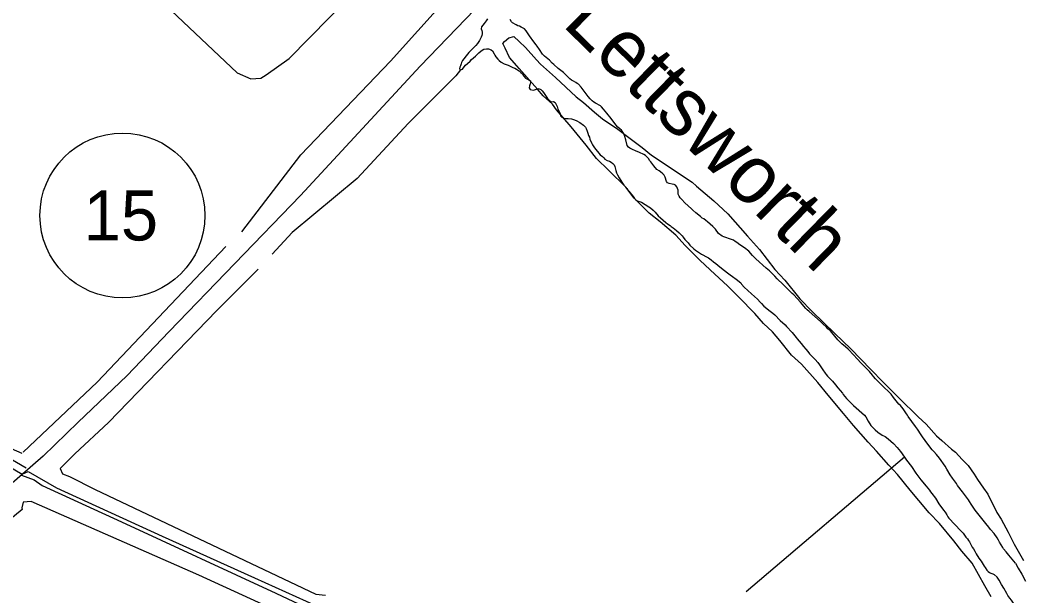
# Model space of a CAD drawing. Extents: x 3161665 to 3199565, y 885729 to 911164.
# Drawn here: x 3167700 to 3169703, y 903568 to 904720 of the extents above; entities that cross this region are included whole.
import ezdxf

# ---------------------------------------------------------------- set-up
doc = ezdxf.new("R2010")
doc.units = 0
for name, color, linetype in [('V-RIVR-IDEN', 7, 'Continuous'), ('V-ROAD-CNTR', 7, 'Continuous'), ('V-ROAD-IDEN', 7, 'Continuous'), ('V-SITE-VEGE', 7, 'Continuous'), ('V-TOPO-SHOR', 7, 'Continuous')]:
    doc.layers.add(name, color=color, linetype=linetype)

msp = doc.modelspace()

# ---------------------------------------------------------------- linework, layer by layer
at = {"layer": 'V-ROAD-CNTR'}
for points in [[(3168682.8, 904817.2), (3168682.1, 904817.3), (3168500.2, 904627.3), (3168260.8, 904368.7), (3167998.1, 904096.6), (3167913.2, 904008.1), (3167816, 903915.2), (3167746.2, 903847.5), (3167631.8, 903748), (3167456.1, 903609.1), (3167355.1, 903531.9), (3167229.6, 903443.7), (3167105.2, 903362.7), (3166973.6, 903283.3), (3166847.9, 903211.6), (3166848.1, 903211.9), (3166676.1, 903125.4), (3166497, 903041.3), (3166200.2, 902917.8), (3166006.1, 902838.5), (3165919.5, 902802.7)], [(3165917.6, 904384.3), (3165969.9, 904376.5), (3166091.1, 904355.3), (3166225.4, 904330.9), (3166351.9, 904300.8), (3166475.2, 904271.7), (3166619.8, 904232), (3166778.1, 904186.6), (3166922.7, 904139.3), (3167057.1, 904090.8), (3167183.4, 904042.2), (3167327.3, 903982.6), (3167459.2, 903926.5), (3167588.6, 903869.4), (3167666.6, 903833.5), (3167704.5, 903811.2)], [(3165919.8, 904399.1), (3165972.3, 904391.3), (3166093.7, 904370.1), (3166228.5, 904345.6), (3166355.4, 904315.4), (3166478.9, 904286.2), (3166623.9, 904246.5), (3166782.5, 904201), (3166927.5, 904153.5), (3167062.3, 904104.9), (3167189, 904056.2), (3167333.1, 903996.5), (3167465.2, 903940.2), (3167594.7, 903883.1), (3167673.5, 903846.8), (3167712.1, 903824.1)], [(3167703, 903809.6), (3167728.2, 903800.1), (3167744.2, 903788.6), (3167902.5, 903716.1), (3168211.5, 903573.2), (3168383, 903492.7), (3168410.7, 903477.2), (3168439.1, 903458.2), (3168484.2, 903425.5), (3168516.8, 903396), (3168566.5, 903352.3), (3168599.2, 903323.2), (3168649.1, 903270.5), (3168697.7, 903213.9), (3168754.3, 903137.6), (3168806.2, 903050.7), (3168857.4, 902953.1), (3168893.3, 902865.9), (3168919.2, 902776.6), (3168937.2, 902680.9), (3168945, 902608.9)], [(3167704.5, 903811.2), (3167716, 903816.7), (3167772.8, 903783.8), (3167983.8, 903687), (3168168.5, 903603.9), (3168293, 903548.2), (3168375.8, 903504.9), (3168429.9, 903476.8), (3168470.8, 903453.3), (3168514, 903420.1), (3168562.2, 903368), (3168623.7, 903312.2), (3168688.9, 903242.9), (3168746.1, 903172.8), (3168783.7, 903113.8), (3168823.8, 903044.9), (3168870.5, 902954.5), (3168900.3, 902877.7), (3168928.1, 902790.3), (3168946.2, 902701.5), (3168955.2, 902630.5)]]:
    msp.add_lwpolyline(points, dxfattribs=at)
at = {"layer": 'V-ROAD-IDEN'}
msp.add_circle((3167904.7, 904328.9), 165, dxfattribs=at)
at = {"layer": 'V-SITE-VEGE'}
for p, q in [((3168668.8, 904676.9), (3168677.4, 904684.2)), ((3168677.4, 904684.2), (3168687.1, 904686.7)), ((3168687.1, 904686.7), (3168698.1, 904676.9)), ((3168665.2, 904673.2), (3168668.8, 904676.9)), ((3168670.1, 904663.4), (3168665.2, 904673.2)), ((3168678.7, 904645.2), (3168670.1, 904663.4)), ((3168698.1, 904676.9), (3168710.3, 904664.8)), ((3168710.3, 904664.8), (3168732.4, 904640.4)), ((3168693.3, 904628.1), (3168678.7, 904645.2)), ((3168698.2, 904623.2), (3168693.3, 904628.1)), ((3168734.9, 904581.8), (3168698.2, 904623.2)), ((3168732.4, 904640.4), (3168740.9, 904631.9)), ((3168740.9, 904631.9), (3168770.3, 904605.1)), ((3168770.3, 904605.1), (3168811.9, 904566.1)), ((3168746, 904568.4), (3168734.9, 904581.8)), ((3168764.3, 904551.4), (3168746, 904568.4)), ((3168811.9, 904566.1), (3168826.5, 904555.2)), ((3168772.9, 904540.4), (3168764.3, 904551.4)), ((3168826.5, 904555.2), (3168848.5, 904535.7)), ((3168802.2, 904506.3), (3168772.9, 904540.4)), ((3168848.5, 904535.7), (3168864.4, 904522.3)), ((3168864.4, 904522.3), (3168895, 904501.7)), ((3168831.6, 904469.8), (3168802.2, 904506.3)), ((3168895, 904501.7), (3168914.5, 904487.1)), ((3168914.5, 904487.1), (3168943.9, 904465.2)), ((3168852.4, 904443), (3168831.6, 904469.8)), ((3168943.9, 904465.2), (3168962.2, 904449.3)), ((3168876.9, 904418.6), (3168852.4, 904443)), ((3168962.2, 904449.3), (3168994, 904428.7)), ((3168994, 904428.7), (3169012.3, 904416.5)), ((3168911.1, 904385.8), (3168876.9, 904418.6)), ((3169012.3, 904416.5), (3169044.1, 904395.8)), ((3168928.2, 904363.8), (3168911.1, 904385.8)), ((3169044.1, 904395.8), (3169052.7, 904387.3)), ((3169052.7, 904387.3), (3169086.9, 904358.1)), ((3168957.6, 904333.4), (3168928.2, 904363.8)), ((3169086.9, 904358.1), (3169115, 904332.5)), ((3168979.6, 904316.4), (3168957.6, 904333.4)), ((3169115, 904332.5), (3169154.2, 904287.5)), ((3169011.4, 904289.6), (3168979.6, 904316.4)), ((3169029.8, 904268.9), (3169011.4, 904289.6)), ((3169154.2, 904287.5), (3169178.6, 904260.7)), ((3169059.1, 904239.7), (3169029.8, 904268.9)), ((3169178.6, 904260.7), (3169209.2, 904220.5)), ((3169079.9, 904220.2), (3169059.1, 904239.7)), ((3169115.4, 904187.3), (3169079.9, 904220.2)), ((3169209.2, 904220.5), (3169228.8, 904199.8)), ((3169137.4, 904165.4), (3169115.4, 904187.3)), ((3169228.8, 904199.8), (3169259.4, 904162)), ((3169169.2, 904132.5), (3169137.4, 904165.4)), ((3169259.4, 904162), (3169283.9, 904136.5)), ((3169186.3, 904113.1), (3169169.2, 904132.5)), ((3169283.9, 904136.5), (3169329.1, 904092.6)), ((3169204.7, 904096), (3169186.3, 904113.1)), ((3169219.3, 904079), (3169204.7, 904096)), ((3169329.1, 904092.6), (3169360.9, 904062.2)), ((3169242.6, 904049.7), (3169219.3, 904079)), ((3169360.9, 904062.2), (3169401.3, 904020.8)), ((3169262.2, 904031.5), (3169242.6, 904049.7)), ((3169295.2, 903994.9), (3169262.2, 904031.5)), ((3169401.3, 904020.8), (3169425.8, 903995.2)), ((3169316, 903969.4), (3169295.2, 903994.9)), ((3169425.8, 903995.2), (3169457.6, 903963.6)), ((3169346.6, 903932.8), (3169316, 903969.4)), ((3169457.6, 903963.6), (3169495.5, 903925.8)), ((3169366.2, 903908.5), (3169346.6, 903932.8)), ((3169495.5, 903925.8), (3169511.4, 903911.2)), ((3169395.5, 903875.6), (3169366.2, 903908.5)), ((3169511.4, 903911.2), (3169532.2, 903888.1)), ((3169532.2, 903888.1), (3169543.2, 903878.4)), ((3169412.6, 903857.3), (3169395.5, 903875.6)), ((3169543.2, 903878.4), (3169562.7, 903861.3)), ((3169562.7, 903861.3), (3169570.1, 903855.2)), ((3169437.1, 903829.3), (3169412.6, 903857.3)), ((3169570.1, 903855.2), (3169583.5, 903840.6)), ((3169454.2, 903811), (3169437.1, 903829.3)), ((3169583.5, 903840.6), (3169595.8, 903828.5)), ((3169595.8, 903828.5), (3169608, 903811.4)), ((3169479.9, 903779.4), (3169454.2, 903811)), ((3169608, 903811.4), (3169614.1, 903800.4)), ((3169614.1, 903800.4), (3169626.4, 903783.4)), ((3169626.4, 903783.4), (3169634.9, 903771.2)), ((3169497.1, 903758.7), (3169479.9, 903779.4)), ((3169634.9, 903771.2), (3169653.3, 903734.6)), ((3169517.9, 903734.3), (3169497.1, 903758.7)), ((3169538.7, 903712.4), (3169517.9, 903734.3)), ((3169653.3, 903734.6), (3169661.9, 903721.2)), ((3169661.9, 903721.2), (3169675.4, 903695.6)), ((3169566.8, 903678.3), (3169538.7, 903712.4)), ((3169675.4, 903695.6), (3169687.6, 903671.2)), ((3169582.7, 903657.6), (3169566.8, 903678.3)), ((3169687.6, 903671.2), (3169706, 903638.3)), ((3169603.5, 903633.2), (3169582.7, 903657.6)), ((3169629.3, 903588.1), (3169603.5, 903633.2)), ((3169641.5, 903566.2), (3169629.3, 903588.1))]:
    msp.add_line(p, q, dxfattribs=at)
at = {"layer": 'V-TOPO-SHOR'}
for p, q in [((3168631.7, 904718.1), (3168627.7, 904713)), ((3167592.2, 903902.6), (3167703.4, 903853.1)), ((3169468.1, 903845.6), (3169151.6, 903576.1))]:
    msp.add_line(p, q, dxfattribs=at)
for points in [[(3167953.8, 904785), (3168134.4, 904614.4), (3168161.1, 904602.6), (3168181.5, 904603.6), (3168192.2, 904610), (3168238.3, 904643.1), (3168318.8, 904725.3), (3168418.6, 904829), (3168444.3, 904850.3), (3168458.2, 904855.7), (3168467.9, 904856.7), (3168463.1, 904882.6)], [(3168143.3, 904296.4), (3168261.4, 904450.3), (3168440.6, 904637.3), (3168550.1, 904759.1), (3168577.4, 904755.4)], [(3168627.7, 904713), (3168622.3, 904706.4), (3168621.7, 904702.3), (3168623.1, 904698.7), (3168623.7, 904695.4), (3168623.7, 904692.1), (3168623, 904688.9), (3168621.8, 904685.5), (3168618.7, 904678.8), (3168614.6, 904673.1), (3168611.4, 904669.1), (3168603, 904660.8), (3168599.9, 904657.3), (3168597.5, 904654.9), (3168594.6, 904651.3), (3168591.9, 904648.4), (3168587.2, 904642.6), (3168584.6, 904638.7), (3168582.5, 904635.1), (3168582.1, 904632), (3168580.7, 904628.6), (3168579, 904625.6), (3168578.8, 904622.5), (3168580.8, 904620.1), (3168584.7, 904621.7), (3168588, 904626.1), (3168590.8, 904629.4), (3168594.7, 904632.8), (3168600, 904637.8), (3168602.5, 904640.7), (3168610.6, 904647.9), (3168613.1, 904650.4), (3168617.4, 904654.2), (3168621.2, 904657.6), (3168624.1, 904659.8), (3168627.2, 904661.5), (3168632.8, 904662.2), (3168636.3, 904662.4), (3168642, 904660.6), (3168644.4, 904658.5), (3168647.8, 904652.4), (3168649.2, 904649.5), (3168651.4, 904646.3), (3168655.3, 904641.4), (3168658.1, 904639.1), (3168661.8, 904635.9), (3168667.8, 904632), (3168676.1, 904629.5), (3168681, 904627.2), (3168685.1, 904625), (3168689.1, 904623.5), (3168698.2, 904618.2), (3168701.5, 904615.1), (3168703.7, 904612.7), (3168705.5, 904610.2), (3168710.9, 904603.7), (3168714.4, 904601.6), (3168717.4, 904600.6), (3168720.3, 904598.6), (3168720.6, 904595.1), (3168720, 904592.1), (3168718.6, 904588.6), (3168717.7, 904584.2), (3168719.7, 904580.7), (3168725.6, 904579.6), (3168728.7, 904580), (3168736.4, 904582.6), (3168741.3, 904580.8), (3168743.9, 904578.5), (3168746.7, 904575.1), (3168752.2, 904566.7), (3168754.8, 904563), (3168759.4, 904558.5), (3168762.7, 904556.5), (3168766.9, 904556.9), (3168769.6, 904555), (3168773.6, 904546.9), (3168775.4, 904541.6), (3168779.8, 904533), (3168780.8, 904528.1), (3168783.4, 904525.5), (3168787.3, 904523.6), (3168791.7, 904522.8), (3168796, 904522.8), (3168802.5, 904522.1), (3168806.8, 904520.7), (3168811.8, 904518.6), (3168819.1, 904514.7), (3168826.6, 904509.8), (3168830.5, 904505.3), (3168832.1, 904502.7), (3168834.1, 904497.8), (3168835.1, 904493.7), (3168836.7, 904489), (3168838.3, 904485.4), (3168839.5, 904481.3), (3168842.9, 904473.2), (3168844.5, 904469.9), (3168848.3, 904464.4), (3168860.2, 904450.3), (3168864.3, 904446.8)], [(3168634.6, 904722.2), (3168631.7, 904718.1)], [(3169020, 904364.5), (3169017.6, 904367.8), (3169016, 904371.2), (3169015.6, 904379.6), (3169014.6, 904383), (3169013.2, 904386.3), (3169010.6, 904389.5), (3169007.8, 904390.6), (3169003.9, 904391.6), (3168998, 904392.9), (3168994.4, 904394.5), (3168992.2, 904397.2), (3168989.6, 904405.5), (3168987.6, 904409.4), (3168984.9, 904412.4), (3168980.7, 904416.3), (3168977.7, 904418), (3168973.2, 904421), (3168967.3, 904428), (3168960.9, 904436.5), (3168958.7, 904439.2), (3168957.1, 904442), (3168950.8, 904449), (3168947.2, 904451.2), (3168938.7, 904455.1), (3168930.3, 904458.2), (3168924.5, 904460.7), (3168919, 904463.8), (3168916.6, 904465.8), (3168914.1, 904468.7), (3168911, 904480.5), (3168909, 904487), (3168907.8, 904490.7), (3168905.4, 904495.8), (3168902.5, 904499.6), (3168899.5, 904502.5), (3168895.5, 904505.6), (3168891, 904510.5), (3168881.7, 904523.1), (3168873.1, 904533.3), (3168866.8, 904541.5), (3168862.6, 904546.2), (3168860.3, 904548.2), (3168850.6, 904553.4), (3168847, 904555.6), (3168843.7, 904558.5), (3168839.9, 904562.4), (3168835.9, 904567), (3168824, 904583.2), (3168822, 904585.6), (3168816.5, 904591.3), (3168814.1, 904593.2), (3168811.4, 904594.8), (3168806.4, 904597.3), (3168802.7, 904599.5), (3168799.5, 904602.2), (3168794.7, 904606.7), (3168786.8, 904614.9), (3168784.1, 904617.1), (3168776.1, 904623), (3168767, 904631), (3168764.1, 904633.7), (3168758.5, 904639.6), (3168748.8, 904647.4), (3168744.5, 904651.9), (3168738.9, 904660.8), (3168734.2, 904667.6), (3168732.2, 904670.2), (3168727.2, 904676.1), (3168718.3, 904688), (3168711.7, 904698.6), (3168708.4, 904702.6), (3168701.6, 904705.7), (3168698.7, 904707.6), (3168695.3, 904708.6), (3168692.2, 904710), (3168684.9, 904714), (3168682.9, 904716.2), (3168679.9, 904720.9)], [(3168580.8, 904620.1), (3168571.2, 904608.1), (3168475.7, 904513), (3168373.7, 904403), (3168244, 904295.1), (3168204.3, 904251.3)], [(3168864.3, 904446.8), (3168866.9, 904444), (3168869.5, 904441.5), (3168874.2, 904439.1), (3168878.8, 904437.4), (3168881.7, 904435.8), (3168885.3, 904432.9), (3168887.7, 904430.2), (3168889.1, 904427), (3168891.1, 904418.8), (3168892.5, 904414.4), (3168894.7, 904409.9), (3168897.9, 904404), (3168903, 904395.8), (3168907, 904389.5), (3168912.9, 904382.8), (3168915.1, 904379.7), (3168917.3, 904377.5), (3168920.1, 904374.2), (3168925.8, 904366.6), (3168928.8, 904363), (3168931.4, 904360.3), (3168933.8, 904358.5), (3168942.6, 904355.2), (3168957.3, 904346.4), (3168960.2, 904344.1), (3168965.6, 904339.6), (3168969.9, 904335.3), (3168975.9, 904328.4), (3168980.2, 904324.3), (3168991.5, 904314.9), (3168994.5, 904312), (3168999.6, 904308.7), (3169002, 904306.7), (3169005.7, 904304.2), (3169012.7, 904298.9), (3169017.6, 904294.4), (3169020.8, 904291.8), (3169024.1, 904288.3), (3169025.7, 904285.6), (3169029.5, 904280.7), (3169035.8, 904274), (3169039.2, 904269.7), (3169046.9, 904262.2), (3169050.3, 904259.5), (3169058.4, 904254.2), (3169062.5, 904251.7), (3169073.6, 904245.8), (3169076.6, 904243.9), (3169081.7, 904240.2), (3169086.7, 904235.9), (3169091.2, 904232.9), (3169098.9, 904226.3), (3169108.2, 904219), (3169114.7, 904214.2), (3169119.5, 904210.2), (3169124.2, 904207.1), (3169131.7, 904201.8), (3169141, 904194.4), (3169142.8, 904191.5), (3169147.6, 904185.6), (3169162.4, 904172.1), (3169174.5, 904161.7), (3169179.7, 904155.6), (3169182.2, 904152.5), (3169187.2, 904147.2), (3169189.6, 904145.2), (3169197.3, 904139.2), (3169205, 904133.5), (3169208.9, 904130.2), (3169219.8, 904119), (3169229.5, 904110.4), (3169232.7, 904107.1), (3169244, 904094.9), (3169251.9, 904084.5), (3169254.1, 904081.8), (3169257.5, 904077.1), (3169261.8, 904072.6), (3169266.4, 904066.9), (3169271.3, 904061.4), (3169275.1, 904056.5), (3169278.3, 904052), (3169283, 904047.1), (3169289.8, 904040.6), (3169295.3, 904034.9), (3169298.5, 904030.4), (3169305.4, 904020.4), (3169310, 904013.3), (3169311.8, 904010.8), (3169314.6, 904007.3), (3169324.1, 903997.3), (3169330.2, 903990.4), (3169335, 903983.9), (3169344.1, 903973.1), (3169345.9, 903970.6), (3169352.6, 903963), (3169359, 903956.1), (3169362.3, 903953), (3169366.1, 903949), (3169388.5, 903929.3), (3169391, 903925.9)], [(3169690.4, 903633.3), (3169676.9, 903649), (3169671.4, 903655.7), (3169666.6, 903662.1), (3169665, 903664.9), (3169658.3, 903675.3), (3169656.5, 903679), (3169653.7, 903683.9), (3169647.5, 903692.8), (3169640.6, 903700.6), (3169637.2, 903705.1), (3169630.7, 903712.8), (3169609.9, 903739.6), (3169601.5, 903751.6), (3169598.2, 903756.9), (3169596.2, 903759.8), (3169584.3, 903776.1), (3169574.7, 903788.5), (3169572.4, 903792.4), (3169564.2, 903803.6), (3169559.5, 903810.3), (3169553.3, 903821.4), (3169549.9, 903827.1), (3169538.6, 903843.4), (3169532.3, 903850.9), (3169527.3, 903856.6), (3169523.9, 903860.1), (3169515.2, 903871.5), (3169504.5, 903886.2), (3169501.5, 903889.9), (3169494.6, 903901.3), (3169490.2, 903906.4), (3169475.9, 903926.6), (3169474.3, 903929.5), (3169472.3, 903931.9), (3169465.6, 903942.3), (3169460.2, 903948.4), (3169457.3, 903951.1), (3169446.4, 903964.8), (3169441.8, 903971.1), (3169437.8, 903975.6), (3169426.2, 903986), (3169414.7, 903997.8), (3169410.5, 904002.3), (3169406.4, 904007), (3169404.2, 904009.1), (3169398.2, 904016.6), (3169392.1, 904022.6), (3169382.4, 904033), (3169372.9, 904042.6), (3169367.1, 904049.1), (3169355.6, 904061.4), (3169350.5, 904066.1), (3169343.4, 904072), (3169334.9, 904080.2), (3169323.4, 904094.6), (3169320.2, 904097.9), (3169315.4, 904102.4), (3169312.7, 904105.3), (3169305.3, 904112.4), (3169300.4, 904116.5), (3169277.6, 904136.6), (3169273.7, 904140.2), (3169271.1, 904143.1), (3169260.6, 904155.3), (3169254.1, 904163.1), (3169247.1, 904170.2), (3169244, 904172.7), (3169237.6, 904178.6), (3169233.7, 904182.7), (3169225.9, 904190.5), (3169214.1, 904202.3), (3169209.3, 904207.4), (3169206.7, 904209.9), (3169198.4, 904218.3), (3169191.7, 904223.8), (3169171.1, 904242.4), (3169164.4, 904249.1), (3169157.2, 904257.5), (3169148.7, 904264), (3169139.3, 904270.2), (3169133.3, 904274.9), (3169129.8, 904277.1), (3169126.8, 904279.4), (3169122.8, 904281), (3169107.1, 904286.4), (3169104.1, 904287.6), (3169096.8, 904292.6), (3169090.2, 904301.3), (3169084.9, 904306.8), (3169074.4, 904316.2), (3169071.4, 904318.7), (3169066.9, 904322), (3169063.9, 904323.8), (3169060.2, 904327.1), (3169051.1, 904334.1), (3169044.9, 904339.6), (3169042.2, 904342.4), (3169029.5, 904354.5), (3169023.4, 904360.6), (3169020, 904364.5)], [(3167706.1, 903855.2), (3167854.1, 903995.1), (3168111.1, 904266.5)], [(3168176.3, 904221.4), (3168093.7, 904139.1), (3167877, 903914.8), (3167809.4, 903851.8), (3167780.4, 903822.9), (3167784.7, 903812.2), (3167798.6, 903806.8), (3167849.9, 903781), (3168291.6, 903571.3), (3168310.9, 903569.1)], [(3169391, 903925.9), (3169395.8, 903917.5), (3169401.4, 903908.7), (3169404.9, 903904.7), (3169409.5, 903900), (3169414.8, 903895.3), (3169423.9, 903889.7), (3169429.7, 903886.4), (3169435.6, 903882.3), (3169446.7, 903872.5), (3169454, 903864.4), (3169460.7, 903856.4), (3169468.1, 903845.6), (3169472.1, 903839.3), (3169482.4, 903826.8), (3169491.3, 903813.4), (3169501.2, 903800.3), (3169511.9, 903787.5), (3169518.1, 903779.5), (3169520.3, 903776), (3169523, 903772.4), (3169530.2, 903763.2), (3169537.1, 903751.8), (3169546.1, 903739.3), (3169549.4, 903735.2), (3169553.2, 903729.7), (3169555.2, 903726.1), (3169557.2, 903723.2), (3169581.3, 903698.3), (3169585.7, 903693.2), (3169591.1, 903685.6), (3169594.4, 903681.8), (3169596.2, 903678.9), (3169598.6, 903675.8), (3169604, 903665.5), (3169606.3, 903662), (3169608.7, 903657.5), (3169610.1, 903654.5), (3169611.9, 903652), (3169617.3, 903643.2), (3169621.6, 903637.3), (3169627.6, 903627.3), (3169629.6, 903624.7), (3169632.8, 903619.4), (3169635.5, 903616.5), (3169638.3, 903614.5), (3169641.3, 903613), (3169645.2, 903612.2), (3169648, 903610.4), (3169653.8, 903605.5)], [(3168507.5, 903386.7), (3168351.4, 903474.8), (3168057.2, 903609.3), (3167722.5, 903756.7), (3167706.4, 903755.6), (3167703.2, 903743.9), (3167704.2, 903740.7), (3167553, 903615.7), (3167292.4, 903424.7), (3167206.6, 903371.3), (3167193.8, 903362.8)], [(3169690.4, 903633.3), (3169695.7, 903623.1), (3169702.7, 903611.1), (3169710.4, 903597.1)], [(3169706.1, 903526.2), (3169702.6, 903530.5), (3169697.4, 903537.7), (3169695.3, 903540.2), (3169692.6, 903544.4), (3169691.1, 903547.2), (3169689.3, 903549.7), (3169686.3, 903553.4), (3169682.1, 903559.4), (3169678.8, 903563.1), (3169675.1, 903568.9), (3169673.3, 903572.6), (3169667.3, 903583.1), (3169662.5, 903590.8), (3169658, 903599), (3169653.8, 903605.5)]]:
    msp.add_lwpolyline(points, dxfattribs=at)

# ---------------------------------------------------------------- texts
at = {"layer": 'V-RIVR-IDEN'}
msp.add_text('Lettsworth', height=116, rotation=315.6367, dxfattribs=at).set_placement((3168781.9, 904710.3))
at = {"layer": 'V-ROAD-IDEN'}
msp.add_text('15', height=100, dxfattribs=at).set_placement((3167827.2, 904278.9))

doc.saveas('drawing.dxf')
